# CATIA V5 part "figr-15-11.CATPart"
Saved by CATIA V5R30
Part number: Part1
Bounding box of the stored display mesh (mm): x -50 to 50, y -32.5 to 33.5, z -52 to 1
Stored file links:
  D:\PROJECTS\CATIA V56R 2020\Resources\Parts File\c15_catia_v5_6r2020_prt\figr-15-11.CATPart
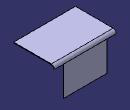
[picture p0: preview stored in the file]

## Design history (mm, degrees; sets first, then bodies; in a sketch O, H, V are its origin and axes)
SheetMetalParameters1: Thickness 1, BendRadius 4, KFactor 0.475772 {= log(min(100,max(20*SheetMetalParameters1.BendRadius,SheetMetalParameters1.Thickness)/SheetMetalParameters1.Thickness))/log(100)/2}, ReliefRadialLength 4, ReliefAxialLength 4, MinimumBendRadius 0
Body1 (main body)
  Sketch1 on xy-plane, origin (0, 0, 0), H (1, 0, 0), V (0, 1, 0)
    line L1 (-50, 32.5) -> (50, 32.5)
    line L2 (50, 32.5) -> (50, -32.5)
    line L3 (50, -32.5) -> (-50, -32.5)
    line L4 (-50, -32.5) -> (-50, 32.5)
    length L1 = 100
    length L2 = 65
    horizontal: L1 H, L3 H
    vertical: L2 V, L4 V
    symmetry: L4 L2 V, L1 L3 H
  Wall1: Thickness 1, Profile Sketch1
  d_NewWallOnEdge1: NewWallOnEdge_Edge edge [face of Wall1 | face of Wall1], NewWallOnEdge_Length 53, NewWallOnEdge_HeightLimitOffset 0, NewWallOnEdge_WidthOffset1 -15, NewWallOnEdge_WidthOffset2 -15, NewWallOnEdge_Angle 90, NewWallOnEdge_BendRadiusValue 4 {= SheetMetalParameters1.BendRadius}, NewWallOnEdge_BendTable SheetMetalParameters1, KFacteur 0.475772 {= log(min(100,max(20*d_NewWallOnEdge1.Radius,SheetMetalParameters1.Thickness)/SheetMetalParameters1.Thickness))/log(100)/2}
